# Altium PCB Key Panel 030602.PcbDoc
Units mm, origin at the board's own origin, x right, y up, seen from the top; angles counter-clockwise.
Board outline 85.73 x 53.97 mm, 2 copper layers (Top Layer, Bottom Layer); 46 components, 37 nets, 135 pads, 39 vias.
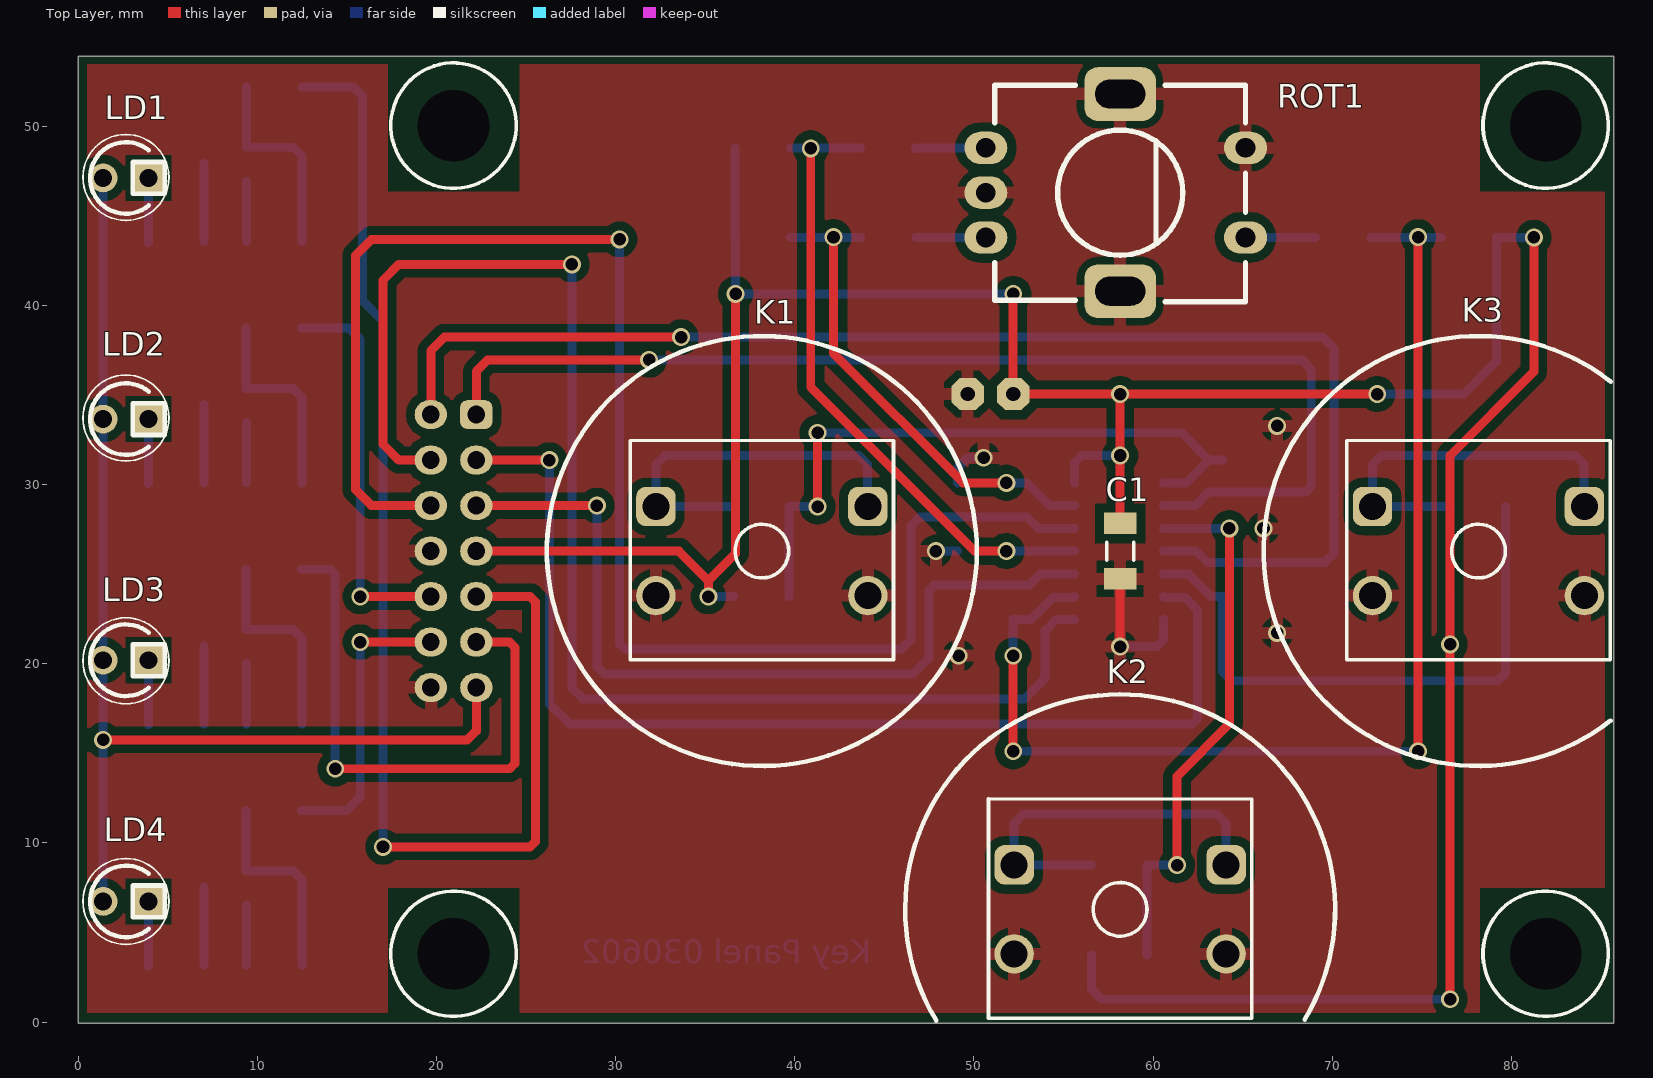
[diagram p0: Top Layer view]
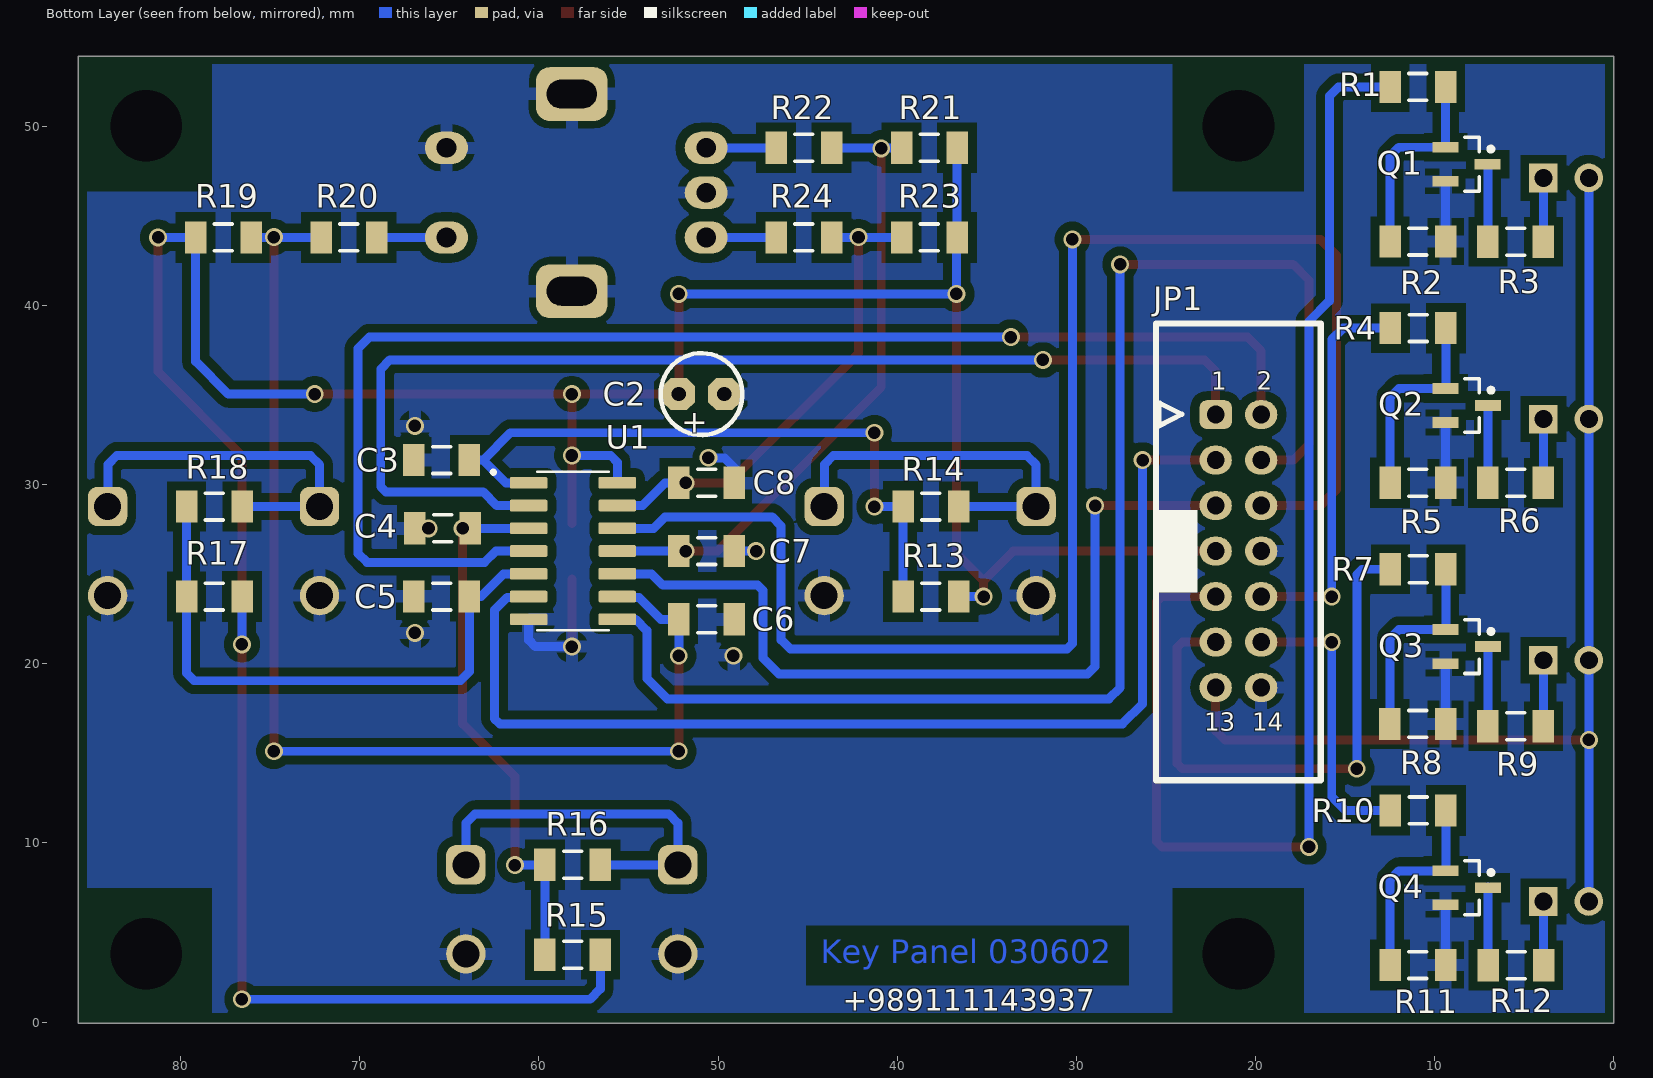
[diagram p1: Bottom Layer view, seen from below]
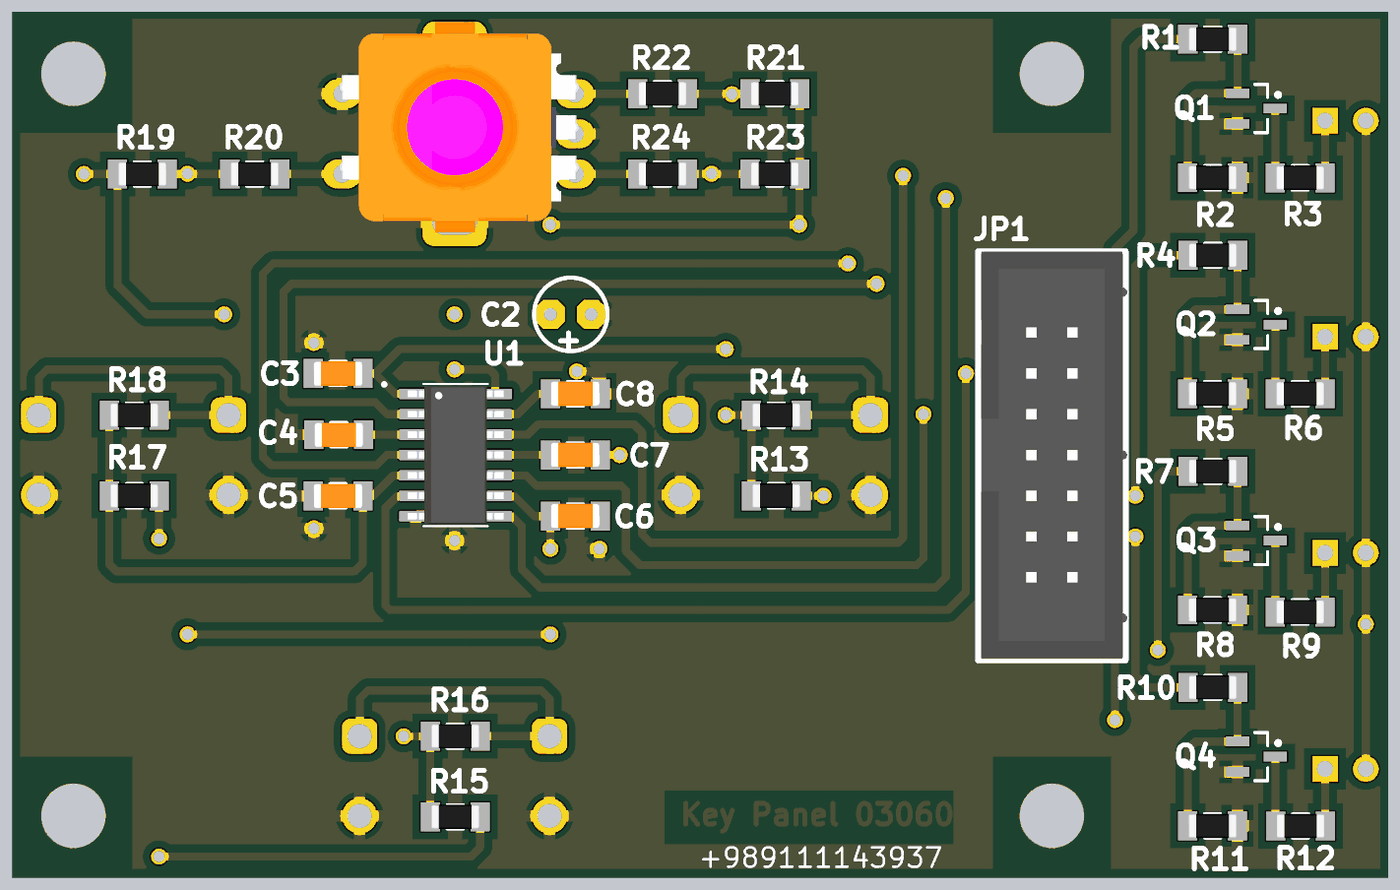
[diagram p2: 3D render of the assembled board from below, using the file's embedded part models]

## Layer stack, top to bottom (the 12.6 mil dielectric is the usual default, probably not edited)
Top Solder: solder mask 0.0102, Solder Resist, Dk 3.5
Top Layer: signal copper 0.0356
Dielectric 1: dielectric 0.32, FR-4, Dk 4.8
Bottom Layer: signal copper 0.0356
Bottom Solder: solder mask 0.0102, Solder Resist, Dk 3.5

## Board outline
0,-0.059 0,53.916 85.725,53.916 85.725,-0.059

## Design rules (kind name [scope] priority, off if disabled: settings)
Clearance [All] p1: gap=0.5 ignorepadtopadclearanceinfootprint=FALSE
PlaneClearance [All] p1: clearance=0.4
PolygonConnect [All] p1: connectstyle=Relief reliefconductorwidth=0.7 reliefentries=4 polygonreliefangle="90 Angle" airgapwidth=0.4
RoutingVias [All] p1: holewidth=0.8 width=1 viastyle="Through Hole" minholewidth=0.5 minwidth=0.6 maxholewidth=1.8 maxwidth=2
SolderMaskExpansion [All] p1: expansion=0.102 istentingtop=FALSE
Width [All] p1: maxlimit=1 minlimit=0.3 preferedwidth=0.5 minimp=50.000000 maximp=50.000000 favimp=50.000000
29 further rules are at their usual default settings.

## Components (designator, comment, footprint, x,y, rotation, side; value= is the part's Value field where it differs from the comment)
C1 "100n" SMD_CAP_1206. 58.166,26.289 r90 top
C2 "10M/25" CAP1p 52.197,35.052 r180 bottom
C3 "100N" SMD_CAP_1206. 65.43,31.369 r180 bottom
C4 "100N" SMD_CAP_1206. 65.38,27.559 r180 bottom
C5 "100N" SMD_CAP_1206. 65.43,23.749 r180 bottom
C6 "100N" SMD_CAP_1206. 50.648,22.479 r0 bottom
C7 "100N" SMD_CAP_1206. 50.648,26.289 r0 bottom
C8 "100N" SMD_CAP_1206. 50.648,30.099 r0 bottom
JP1 "Key LED" IDC14-BOX 20.955,26.289 r180 bottom
K1 "Left" SW-12*14 38.166,26.289 r0 top locked
K2 "Left" SW-12*14 58.166,6.289 r0 top locked
K3 "Left" SW-12*14 78.166,26.289 r0 top locked
LD1 "Red" LED3 2.667,47.117 r0 top
LD2 "Red" LED3 2.667,33.655 r0 top
LD3 "Red" LED3 2.667,20.193 r0 top
LD4 "Red" LED3 2.667,6.731 r0 top
Q1 "2N2222" 2N2222 9.917,47.979 r270 bottom
Q2 "2N2222" 2N2222 9.911,34.517 r270 bottom
Q3 "2N2222" 2N2222 9.911,21.055 r270 bottom
Q4 "2N2222" 2N2222 9.911,7.593 r270 bottom
R1 "5K" "RES 1206" 10.935,52.197 r0 bottom
R2 "10K" "RES 1206" 10.941,43.567 r0 bottom
R3 "470R" "RES 1206" 5.486,43.561 r180 bottom
R4 "5K" "RES 1206" 10.929,38.735 r0 bottom
R5 "10K" "RES 1206" 10.941,30.105 r0 bottom
R6 "470R" "RES 1206" 5.486,30.099 r180 bottom
R7 "5K" "RES 1206" 10.929,25.273 r0 bottom
R8 "10K" "RES 1206" 10.947,16.637 r0 bottom
R9 "470R" "RES 1206" 5.486,16.51 r180 bottom
R10 "5K" "RES 1206" 10.929,11.811 r0 bottom
R11 "10K" "RES 1206" 10.941,3.181 r0 bottom
R12 "470R" "RES 1206" 5.461,3.175 r180 bottom
R13 "10K" "RES 1206" 38.125,23.749 r180 bottom
R14 "10K" "RES 1206" 38.125,28.774 r180 bottom
R15 "10K" "RES 1206" 58.125,3.749 r180 bottom
R16 "10K" "RES 1206" 58.125,8.774 r180 bottom
R17 "10K" "RES 1206" 78.125,23.749 r180 bottom
R18 "10K" "RES 1206" 78.125,28.774 r180 bottom
R19 "10K" "RES 1206" 77.619,43.796 r0 bottom
R20 "10K" "RES 1206" 70.618,43.796 r180 bottom
R21 "10K" "RES 1206" 38.213,48.796 r180 bottom
R22 "10K" "RES 1206" 45.214,48.796 r180 bottom
R23 "10K" "RES 1206" 38.213,43.796 r0 bottom
R24 "10K" "RES 1206" 45.214,43.796 r180 bottom
ROT1 "Alps Rotary" EC11 58.166,46.296 r270 top locked
U1 "CD40106BE" SOIC-14PIN 58.104,26.255 r180 bottom locked

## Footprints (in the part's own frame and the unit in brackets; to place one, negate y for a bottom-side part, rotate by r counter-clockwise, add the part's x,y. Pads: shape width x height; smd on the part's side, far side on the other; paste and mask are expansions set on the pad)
2N2222 [mm] "SOT_23"
  rect 0.6x1.45 smd: 1(-0.85,0.525) 2(1.05,0.525) 3(0.1,2.875)
  silkscreen extent -1.4,1.6 1.6,3.17, body extent -1.4,1 1.6,2.4, height 1.1
CAP1p [mm]
  oct 1.8x1.8 hole 0.8: 1(0,0) 2(2.54,0)
  silkscreen extent -1.02,-2.29 3.55,2.29
EC11 [mm]
  oval 1.8x2.4 hole 1.1: 1(-2.5,-7.5) 2(0,-7.5) 3(2.5,-7.5) 4(-2.5,7) 5(2.5,7)
  rrect50% 3x4 hole 1.6 slot 2.8 at 90 deg: 6(-5.5,0) 7(5.5,0)
  silkscreen extent -6,-7 6.1,7, body extent -6.54,-7.75 6.56,7.2, height 24.5
IDC14-BOX [mm]
  rrect50% 1.8x1.6 hole 1: 1(-1.27,7.62)
  oval 1.8x1.6 hole 1: 2(1.27,7.62) 3(-1.27,5.08) 4(1.27,5.08) 5(-1.27,2.54) 6(1.27,2.54) 7(-1.27,0) 8(1.27,0) 9(-1.27,-2.54) 10(1.27,-2.54) 11(-1.27,-5.08) 12(1.27,-5.08) 13(-1.27,-7.62) 14(1.27,-7.62)
  silkscreen extent -4.6,-12.8 4.6,12.7, body extent -4.4,-12.69 4.7,12.69, height 3.1
LED3 [mm]
  round 1.6 hole 1: 1(-1.27,0)
  rect 1.6x1.6 hole 1: 2(1.27,0)
  silkscreen extent -2,-2 2.16,2
"RES 1206" [mm] "Chip Resistor, 2-Leads, Body 3.2x1.6mm, IPC High Density _ (0.125 W)"
  rect 1.2x1.8 smd: 1(-1.549,0) 2(1.549,0)
  silkscreen extent -0.5,-0.75 0.5,0.75, body extent -1.52,-0.76 1.52,0.76, height 0.6
SMD_CAP_1206. [mm]
  rect 1.2x1.8 smd: 1(-1.549,0) 2(1.549,0)
  silkscreen extent -0.5,-0.75 0.5,0.75, body extent -1.52,-0.77 1.53,0.75, height 0.75
SOIC-14PIN [mm]
  rrect25% 2.1x0.65 smd: 1(-2.475,3.844) 2(-2.475,2.574) 3(-2.475,1.304) 4(-2.475,0.034) 5(-2.475,-1.236) 6(-2.475,-2.506) 7(-2.475,-3.776) 8(2.475,-3.776) 9(2.475,-2.506) 10(2.475,-1.236) 11(2.475,0.034) 12(2.475,1.304) 13(2.475,2.574) 14(2.475,3.844)
  silkscreen extent -4.54,-4.39 2,4.53, body extent -3,-4.29 3,4.36, height 1.75
SW-12*14 [mm]
  rrect50% 2.2x2.2 hole 1.5: 1(-5.916,2.485) 1(5.916,2.485)
  round 2.2 hole 1.5: 2(-5.916,-2.485) 2(5.916,-2.485)
  silkscreen extent -7.35,-6.07 7.35,6.17

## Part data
C1 C3 C4 C5 C6 C7 C8: library part C
C2: library part "Cap Pol1 _ SMD", "SMD Polarized Capacitor"
JP1: library part "Header 7X2", "Header, 7-Pin, Dual row"
K1 K2 K3: library part "Switch PB", "Push Button Switch"
LD1 LD2 LD3 LD4: library part LED, "LED"
Q1 Q2 Q3 Q4: library part N
R1 R2 R3 R4 R5 R6 R7 R8 R9 R10 R11 R12 R13 R14 R15 R16 R17 R18 R19 R20 R21 R22 R23 R24: library part Resistor, "Resistor", Power="1/8 W", Tolerance=5%
ROT1: library part AlpsRotary
U1: "CMOS Hex Schmitt Triggers 14-PDIP -55 to 125", Package="PDIP-14 Texas Instruments"

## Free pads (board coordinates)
  oval 3.5x3 hole 4: ""(20.955,3.81) ""(20.955,50.038) ""(81.915,3.81)
  round 3.5 hole 4: ""(81.915,50.038)

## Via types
v1: diameter 1, hole 0.7, Top Layer to Bottom Layer, 39 vias

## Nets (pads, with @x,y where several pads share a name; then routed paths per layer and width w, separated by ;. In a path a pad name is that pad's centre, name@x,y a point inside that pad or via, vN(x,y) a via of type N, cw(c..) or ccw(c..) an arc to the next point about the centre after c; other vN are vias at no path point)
3V3: C1.2 C2.1 JP1.7 R13.2 R15.2 R17.2 R19.2 R21.2 R23.1 U1.14 | length 178.9
  Top Layer w0.5: JP1.7 33.528,26.289 35.179,24.638 ; v1(35.179,23.749) 35.179,24.638 ; v1(36.703,40.64) 36.703,26.162 35.179,24.638 ; v1(52.197,40.64) C2.1 v1(58.166,35.052) ; C1.2 v1(58.166,31.623) v1(58.166,35.052) ; v1(72.517,35.052) v1(58.166,35.052) ; v1(76.581,1.27) v1(76.581,21.082) 76.581,31.623 81.261,36.303 v1(81.261,43.796)
  Bottom Layer w0.5: v1(35.179,23.749) R13.2 ; R21.2 R23.1 36.683,43.776 36.683,40.66 v1(36.703,40.64) v1(52.197,40.64) ; U1.14 55.629,31.245 56.007,31.623 v1(58.166,31.623) ; R15.2 56.576,1.844 57.15,1.27 v1(76.581,1.27) ; v1(72.517,35.052) 77.343,35.052 79.168,36.877 R19.2 v1(81.261,43.796) ; R17.2 76.579,23.747 76.579,21.084 v1(76.581,21.082)
GND: C1.1 C2.2 C3.1 C4.1 C5.1 C6.1 C7.1 C8.1 JP1.8 JP1.14 K1.2 K2.2 K3.2 Q1.2 Q2.2 Q3.2 Q4.2 R2.1 R5.1 R8.1 R11.1 ROT1.2 ROT1.4 ROT1.6 ROT1.7 U1.7 | length 24.7
  Top Layer w0.5: v1(58.166,20.955) C1.1
  Bottom Layer w0.5: Q3.2 9.392,20.005 9.392,16.643 R8.1 ; R11.1 Q4.2@9.392,6.543 ; R5.1 Q2.2@9.392,33.467 ; R2.1 Q1.2 ; v1(47.879,26.289) C7.1 ; C8.1 49.098,30.937 49.657,31.496 v1(50.546,31.496) ; v1(58.166,20.955) 60.201,20.955 60.579,21.333 U1.7
  other v1: 49.149,20.447 66.929,21.717 66.167,27.559 66.929,33.274
K1: C3.2 R13.1 R14.1 U1.1 | length 37
  Top Layer w0.5: v1(41.275,28.774) v1(41.275,32.893)
  Bottom Layer w0.5: R13.1 R14.1 v1(41.275,28.774) ; v1(41.275,32.893) 61.595,32.893 63.119,31.369 ; U1.1 61.849,30.099 63.119,31.369 ; C3.2 63.119,31.369
K2: C4.2 R15.1 R16.1 U1.3 | length 29.9
  Top Layer w0.5: v1(61.341,8.763) 61.341,13.716 64.262,16.637 v1(64.262,27.559)
  Bottom Layer w0.5: R15.1 R16.1 R16.1@59.685,8.764 ; R16.1@59.675,8.764 R16.1@59.685,8.764 ; R16.1@59.686,8.763 R16.1@59.685,8.764 ; U1.3 C4.2 ; v1@61.276,8.764 R16.1@59.685,8.764
K3: C5.2 R17.1 R18.1 U1.5 | length 33.5
  Bottom Layer w0.5: U1.5 61.976,25.019 63.246,23.749 C5.2 63.881,19.558 64.389,19.05 79.248,19.05 79.675,19.477 R18.1
K4: C6.2 R19.1 R20.1 U1.9 | length 66.5
  Top Layer w0.5: v1(52.197,15.113) v1(52.197,20.447) ; v1(74.803,15.113) v1(74.803,43.815)
  Bottom Layer w0.5: v1(52.197,15.113) v1(74.803,15.113) ; v1(52.197,20.447) C6.2 53.196,22.479 54.421,23.704 55.584,23.704 U1.9 ; R20.1 R19.1
KEY1: JP1.1 U1.2 | length 64.8
  Top Layer w0.5: JP1.1 22.225,36.322 22.86,36.957 v1(31.877,36.957)
  Bottom Layer w0.5: v1(31.877,36.957) 68.326,36.957 68.834,36.449 68.834,29.884 68.541,29.591 63.119,29.591 62.357,28.829 U1.2
KEY2: JP1.2 U1.4 | length 76
  Top Layer w0.5: JP1.2 19.685,37.465 20.447,38.227 v1(33.655,38.227)
  Bottom Layer w0.5: v1(33.655,38.227) 69.469,38.227 70.104,37.592 70.104,26.162 69.596,25.654 63.042,25.654 62.407,26.289 U1.4
KEY3: JP1.3 U1.6 | length 62.7
  Top Layer w0.5: JP1.3 v1(26.309,31.369)
  Bottom Layer w0.5: v1(26.309,31.369) 26.309,17.76 27.432,16.637 62.191,16.637 62.484,16.93 62.484,22.987 61.767,23.704 60.624,23.704 U1.6
KEY4: JP1.4 U1.8 | length 78.4
  Top Layer w0.5: JP1.4 17.907,31.369 17.018,32.258 17.018,41.402 17.907,42.291 v1(27.559,42.291)
  Bottom Layer w0.5: v1(27.559,42.291) 27.559,18.669 28.194,18.034 52.832,18.034 53.975,19.177 53.975,21.844 54.61,22.479 U1.8
LED1: JP1.9 R1.2 | length 71.4
  Top Layer w0.5: v1(17.018,9.779) 25.234,9.779 25.527,10.072 25.527,23.456 25.234,23.749 JP1.9
  Bottom Layer w0.5: R1.2 15.367,52.197 15.875,51.689 15.875,40.259 17.018,39.116 v1(17.018,9.779)
LED2: JP1.10 R4.2 | length 21.8
  Top Layer w0.5: v1(15.748,23.749) JP1.10
  Bottom Layer w0.5: R4.2 15.113,38.735 15.748,38.1 v1(15.748,23.749)
LED3: JP1.11 R7.2 | length 31.8
  Top Layer w0.5: v1(14.351,14.137) 24.091,14.137 24.384,14.43 24.384,20.916 24.091,21.209 JP1.11
  Bottom Layer w0.5: R7.2 14.058,25.273 14.351,24.98 v1(14.351,14.137)
LED4: JP1.12 R10.2 | length 16.2
  Top Layer w0.5: v1(15.748,21.209) JP1.12
  Bottom Layer w0.5: R10.2 14.986,11.811 15.748,12.573 v1(15.748,21.209)
NetK1_1: K1.1 R14.2 | length 21.2
  Bottom Layer w0.5: R14.2 32.25,28.774 32.25,31.107 32.766,31.623 43.561,31.623 44.069,31.115 44.069,28.787 K1.1@44.082,28.774
NetK2_1: K2.1 R16.2 | length 21.2
  Bottom Layer w0.5: R16.2 52.25,8.774 52.25,11.107 52.766,11.623 63.561,11.623 64.069,11.115 64.069,8.787 K2.1@64.082,8.774
NetK3_1: K3.1 R18.2 | length 21.2
  Bottom Layer w0.5: R18.2 72.25,28.774 72.25,31.107 72.766,31.623 83.561,31.623 84.069,31.115 84.069,28.787 K3.1@84.082,28.774
NetLD1_2: LD1.2 R3.2 | length 3.6
  Bottom Layer w0.5: R3.2@3.937,43.517 LD1.2
NetLD2_2: LD2.2 R6.2 | length 3.6
  Bottom Layer w0.5: R6.2@3.937,30.055 LD2.2
NetLD3_2: LD3.2 R9.2 | length 3.6
  Bottom Layer w0.5: R9.2@3.937,16.593 LD3.2
NetLD4_2: LD4.2 R12.2 | length 3.6
  Bottom Layer w0.5: R12.2@3.937,3.131 LD4.2
NetQ1_1: Q1.1 R1.1 R2.2 | length 11.4
  Bottom Layer w0.5: Q1.1@9.386,48.835 R1.1 ; Q1.1 12.004,48.829 12.491,48.342 R2.2
NetQ1_3: Q1.3 R3.1 | length 4.4
  Bottom Layer w0.5: R3.1 Q1.3@7.036,47.923
NetQ2_1: Q2.1 R4.1 R5.2 | length 11.4
  Bottom Layer w0.5: Q2.1@9.38,35.373 R4.1 ; Q2.1@9.392,35.361 12.004,35.361 12.491,34.874 R5.2@12.491,30.099
NetQ2_3: Q2.3 R6.1 | length 4.4
  Bottom Layer w0.5: R6.1 Q2.3@7.036,34.461
NetQ3_1: Q3.1 R7.1 R8.2 | length 11.4
  Bottom Layer w0.5: Q3.1@9.38,21.911 R7.1 ; Q3.1@9.392,21.899 12.004,21.899 12.491,21.412 R8.2@12.491,16.637
NetQ3_3: Q3.3 R9.1 | length 4.4
  Bottom Layer w0.5: R9.1@7.036,16.637 Q3.3@7.036,20.999
NetQ4_1: Q4.1 R10.1 R11.2 | length 11.4
  Bottom Layer w0.5: Q4.1@9.38,8.449 R10.1 ; Q4.1@9.392,8.437 12.004,8.437 12.491,7.95 R11.2@12.491,3.175
NetQ4_3: Q4.3 R12.1 | length 4.4
  Bottom Layer w0.5: R12.1@7.036,3.175 Q4.3@7.036,7.537
NetR20_2: R20.2 ROT1.5 | length 3.9
  Bottom Layer w0.5: ROT1.5 R20.2
NetR22_1: R22.1 ROT1.1 | length 3.9
  Bottom Layer w0.5: R22.1@46.736,48.768 R22.1 ROT1.1
NetR24_1: R24.1 ROT1.3 | length 3.9
  Bottom Layer w0.5: R24.1 ROT1.3
RKY1: JP1.5 U1.10 | length 47.1
  Top Layer w0.5: JP1.5 v1(28.956,28.829)
  Bottom Layer w0.5: v1(28.956,28.829) 28.956,19.851 29.376,19.431 46.609,19.431 47.498,20.32 47.498,24.091 47.791,24.384 53.086,24.384 53.721,25.019 U1.10
RKY2: JP1.6 U1.12 | length 87.9
  Top Layer w0.5: JP1.6 16.383,28.829 15.494,29.718 15.494,42.799 16.383,43.688 v1(30.226,43.688)
  Bottom Layer w0.5: v1(30.226,43.688) 30.226,21.121 30.519,20.828 45.974,20.828 46.482,21.336 46.482,27.686 46.99,28.194 52.959,28.194 53.594,27.559 U1.12
RY1: C7.2 R21.1 R22.2 U1.11 | length 35.4
  Top Layer w0.5: v1(40.894,48.768) 40.894,35.433 50.038,26.289 v1(51.816,26.289)
  Bottom Layer w0.5: R21.1 R22.2 ; C7.2 U1.11
RY2: C8.2 R23.2 R24.2 U1.13 | length 27
  Top Layer w0.5: v1(42.164,43.815) 42.164,37.338 49.403,30.099 v1(51.816,30.099)
  Bottom Layer w0.5: R23.2 R24.2 ; C8.2 52.959,30.099 54.229,28.829 U1.13
VP5: JP1.13 LD1.1 LD2.1 LD3.1 LD4.1 | length 63.8
  Top Layer w0.5: v1(1.397,15.748) 21.717,15.748 22.225,16.256 JP1.13
  Bottom Layer w0.5: LD4.1 LD3.1 LD2.1 LD1.1

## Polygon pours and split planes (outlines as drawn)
GND on Top Layer "NONET_L-01_P-001" (solid, pour order 2): 0.508,53.467 85.217,53.467 85.217,0.508 0.508,0.508
GND on Bottom Layer "NONET_L-01_P-001" (solid, pour order 0): 0.508,53.467 85.217,53.467 85.217,0.508 0.508,0.508

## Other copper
Top Layer:
  pour cut-out: 17.272,7.493 17.272,0.127 24.638,0.127 24.638,7.493
  pour cut-out: 78.232,7.493 78.232,0.127 85.598,0.127 85.598,7.493
  pour cut-out: 78.232,53.721 78.232,46.355 85.598,46.355 85.598,53.721
  pour cut-out: 17.272,53.721 17.272,46.355 24.638,46.355 24.638,53.721
Bottom Layer:
  pour cut-out: 17.272,7.493 17.272,0.127 24.638,0.127 24.638,7.493
  pour cut-out: 78.232,7.493 78.232,0.127 85.598,0.127 85.598,7.493
  pour cut-out: 78.232,53.721 78.232,46.355 85.598,46.355 85.598,53.721
  pour cut-out: 17.272,53.721 17.272,46.355 24.638,46.355 24.638,53.721
  text "Key Panel 030602" at 44.277,3.273 h1.3

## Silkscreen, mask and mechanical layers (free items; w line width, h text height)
Top Overlay:
  circle w0.254: c38.166,26.289 r12
  circle w0.1: c2.667,6.732 r2.4
  circle w0.1: c2.667,20.161 r2.4
  circle w0.1: c2.667,33.717 r2.4
  circle w0.1: c2.667,47.146 r2.4
  lines w0.2: 18.485,6.289 ccw(c20.955,3.81) 18.498,6.303 ; 18.485,52.517 ccw(c20.955,50.038) 18.498,52.531 ; 79.445,1.331 cw(c81.915,3.81) 79.458,1.317 ; 79.445,52.517 ccw(c81.915,50.038) 79.458,52.531
  lines w0.254: 47.906,0.066 cw(c58.166,6.289) 68.46,0.123 ; 85.548,16.828 cw(c78.166,26.289) 85.548,35.75
Bottom Overlay:
  text "+989111143937" at 43.053,0.635 h1.2
Mechanical 1:
  lines w0.1: 0,0 0,53.916 85.725,53.916 85.725,0 0,0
